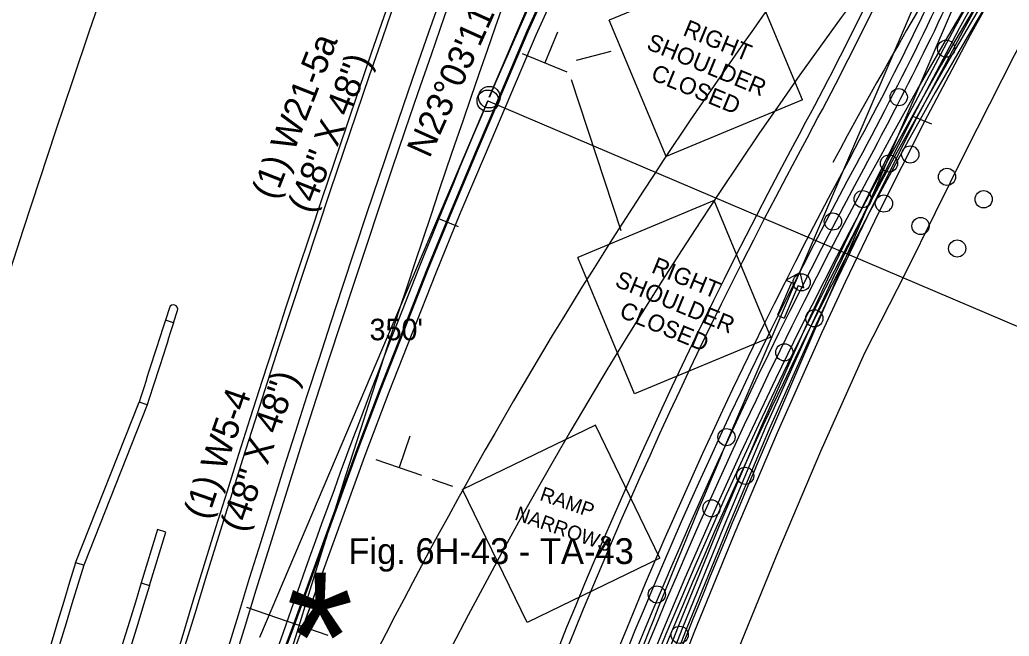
# Model space of a CAD drawing. Extents: x 659657 to 668193, y 633084 to 648639.
# Drawn here: x 661546.4 to 661776.7, y 641104.4 to 641247.7 of the extents above; entities that cross this region are included whole.
import ezdxf

# ---------------------------------------------------------------- set-up
doc = ezdxf.new("R2010")
doc.units = 0
for name, color, linetype in [('R_Border Prem', 7, 'Continuous'), ('R_Draft', 7, 'Continuous'), ('R_MOT_Stage 1A', 7, 'Continuous'), ('R_MOT_Stage 1A_Striping', 7, 'Continuous'), ('R_MOT_Stage 1B', 7, 'Continuous'), ('R_MOT_Stage 1B_Striping', 7, 'Continuous'), ('R_MOT_Stage 1C', 7, 'Continuous'), ('R_MOT_Stage 1C_Striping', 7, 'Continuous'), ('R_MOT_Stage 2', 7, 'Continuous'), ('R_MOT_Stage 2_Striping_PPM', 7, 'Continuous'), ('R_MOT_Stage 3_Striping_PPM', 7, 'Continuous'), ('R_MOT_Stage 4_Striping_PPM', 7, 'Continuous'), ('R_MOT_Stage 5_Striping_PPM', 7, 'Continuous'), ('S_EXISTING_ALIGNMENT', 7, 'Continuous'), ('T_SIGNAL CONTROL CABINET', 7, 'Continuous'), ('TEMP_DETECTION ZONE_Stage 2', 7, 'Continuous'), ('TEMP_SIGNAL_POLES_STAGE 3', 7, 'Continuous'), ('TEXT_TEMP_SIGNAL_POLES_STAGE 2', 7, 'Continuous')]:
    doc.layers.add(name, color=color, linetype=linetype)

msp = doc.modelspace()

# ---------------------------------------------------------------- linework, layer by layer
at = {"layer": 'R_Border Prem'}
msp.add_arc((665219.85, 639999.01), 3863.72, 156.12343, 201.98495, dxfattribs=at)
at = {"layer": 'R_MOT_Stage 1A'}
for points in [[(661690.86, 641084.08), (661699.68, 641106.74), (661709.23, 641130.12), (661719.07, 641153.39), (661729.49, 641176.72), (661734.96, 641188.51), (661742.81, 641204.85), (661753.48, 641226.01), (661764.17, 641246.15), (661771.4, 641259.24), (661776.94, 641268.8), (661789.32, 641290.7), (661801.96, 641312.47), (661814.78, 641334.13), (661827.85, 641355.66), (661841.14, 641377), (661849.52, 641390.35)], [(661692.73, 641083.37), (661701.54, 641106), (661711.08, 641129.35), (661720.91, 641152.59), (661731.31, 641175.89), (661736.77, 641187.66), (661744.61, 641203.96), (661755.26, 641225.09), (661765.93, 641245.2), (661773.14, 641258.26), (661778.67, 641267.8), (661791.06, 641289.7), (661803.68, 641311.46), (661816.49, 641333.1), (661829.55, 641354.62), (661842.83, 641375.94), (661851.27, 641389.37)]]:
    msp.add_lwpolyline(points, dxfattribs=at)
for centre in [(661748.71, 641214.33), (661731.33, 641178.31), (661715.22, 641141.7), (661699.97, 641104.72)]:
    msp.add_circle(centre, 2, dxfattribs=at)
at = {"layer": 'R_MOT_Stage 1A_Striping'}
for p, q in [((661655.68, 641229.74), (661701.73, 641337.94)), ((661655.68, 641229.74), (661701.73, 641337.94)), ((661602.25, 641104.17), (661655.32, 641228.89)), ((661602.25, 641104.17), (661655.32, 641228.89))]:
    msp.add_line(p, q, dxfattribs=at)
for points in [[(661694.6, 641082.67), (661703.39, 641105.26), (661712.93, 641128.58), (661722.74, 641151.79), (661733.13, 641175.06), (661738.57, 641186.8), (661746.4, 641203.08), (661757.03, 641224.17), (661767.69, 641244.25), (661774.88, 641257.27), (661780.41, 641266.81), (661792.8, 641288.71), (661805.41, 641310.45), (661818.21, 641332.07), (661831.26, 641353.57), (661844.53, 641374.88), (661853.01, 641388.39)], [(661713.61, 641101.19), (661723.08, 641124.36), (661732.83, 641147.42), (661743.05, 641170.31), (661752.62, 641188.93), (661766.4, 641216.91), (661777.94, 641239.5), (661790.01, 641261.46), (661802.34, 641283.25), (661814.9, 641304.89), (661827.64, 641326.42), (661840.62, 641347.81), (661853.85, 641369.05), (661862.25, 641382.42)], [(661655.32, 641228.89), (661867.57, 641138.56)], [(661758.71, 641223.46), (661754.08, 641225.35)], [(661599.17, 641111.17), (661618.06, 641104.61)]]:
    msp.add_lwpolyline(points, dxfattribs=at)
for centre in [(661655.68, 641229.74), (661655.32, 641228.89)]:
    msp.add_circle(centre, 2.5, dxfattribs=at)
for centre, radius, start, end in [((662973.69, 640668.84), 1432.39, 147.56037, 156.947), ((663412.67, 640481.02), 1909.86, 156.947, 165.06575)]:
    msp.add_arc(centre, radius, start, end, dxfattribs=at)
at = {"layer": 'R_MOT_Stage 1B'}
for centre in [(661750.97, 641229.73), (661753.65, 641216.42), (661762.19, 641211.21), (661747.52, 641205), (661770.73, 641206), (661735.65, 641200.81), (661756.05, 641199.77), (661764.58, 641194.55), (661728.36, 641186.68), (661710.89, 641150.68), (661694.67, 641114.1)]:
    msp.add_circle(centre, 2, dxfattribs=at)
for centre, radius, start, end in [((661058.38, 641584.99), 761.94, 331.55776, 336.77389), ((661058.38, 641584.99), 776.94, 331.55776, 336.77389), ((661058.38, 641584.99), 778.94, 331.55776, 336.15299), ((662755.3, 640665.85), 1167.92, 151.55776, 169.05116), ((662755.3, 640665.85), 1152.92, 151.55776, 169.05116), ((662755.3, 640665.85), 1150.92, 151.55776, 169.05116)]:
    msp.add_arc(centre, radius, start, end, dxfattribs=at)
at = {"layer": 'R_MOT_Stage 1B_Striping'}
for p, q in [((661655.68, 641229.74), (661701.73, 641337.94)), ((661655.68, 641229.74), (661701.73, 641337.94)), ((661602.25, 641104.17), (661655.32, 641228.89)), ((661602.25, 641104.17), (661655.32, 641228.89))]:
    msp.add_line(p, q, dxfattribs=at)
for points in [[(661655.32, 641228.89), (661867.57, 641138.56)], [(661648.53, 641199.56), (661643.9, 641201.45)], [(661599.17, 641111.17), (661618.06, 641104.61)]]:
    msp.add_lwpolyline(points, dxfattribs=at)
for centre in [(661655.68, 641229.74), (661655.32, 641228.89)]:
    msp.add_circle(centre, 2.5, dxfattribs=at)
for centre, radius, start, end in [((662973.69, 640668.84), 1432.39, 147.56037, 156.947), ((661058.38, 641584.99), 763.94, 331.55776, 336.77389), ((661058.38, 641584.99), 774.94, 331.55776, 336.77389), ((663412.67, 640481.02), 1909.86, 156.947, 165.06575), ((662755.3, 640665.85), 1165.92, 151.55776, 169.05116), ((662755.3, 640665.85), 1154.92, 151.55776, 169.05116)]:
    msp.add_arc(centre, radius, start, end, dxfattribs=at)
at = {"layer": 'R_MOT_Stage 1C'}
for points in [[(661599.69, 641078.64), (661609.82, 641105.49), (661614.93, 641119.59), (661620.04, 641133.7), (661625.17, 641147.83), (661630.51, 641161.92), (661635.87, 641175.5), (661641.39, 641189.49), (661647.07, 641203.44), (661652.96, 641217.3), (661658.83, 641231.15), (661664.71, 641245.03), (661670.95, 641258.81), (661677.34, 641272.5), (661681.59, 641281.56)], [(661601.61, 641078.07), (661611.69, 641104.8), (661616.81, 641118.91), (661621.92, 641133.02), (661627.04, 641147.14), (661632.37, 641161.19), (661637.73, 641174.77), (661643.24, 641188.74), (661648.92, 641202.67), (661654.8, 641216.52), (661660.67, 641230.37), (661666.55, 641244.23), (661672.77, 641257.97), (661679.15, 641271.66), (661683.4, 641280.71)], [(661614.93, 641119.59), (661620.04, 641133.7), (661625.17, 641147.83), (661630.51, 641161.92), (661635.87, 641175.5), (661641.39, 641189.49), (661647.07, 641203.44), (661652.96, 641217.3), (661658.83, 641231.15), (661664.71, 641245.03), (661670.95, 641258.81), (661677.34, 641272.5), (661681.59, 641281.56)], [(661616.81, 641118.91), (661621.92, 641133.02), (661627.04, 641147.14), (661632.37, 641161.19), (661637.73, 641174.77), (661643.24, 641188.74), (661648.92, 641202.67), (661654.8, 641216.52), (661660.67, 641230.37), (661666.55, 641244.23), (661672.77, 641257.97), (661679.15, 641271.66), (661683.4, 641280.71)], [(661610.34, 641106.95), (661614.93, 641119.59)], [(661612.24, 641106.31), (661616.81, 641118.91)]]:
    msp.add_lwpolyline(points, dxfattribs=at)
for centre in [(661762.02, 641241.02), (661742.57, 641206.03), (661724.35, 641170.39), (661707.38, 641134.14)]:
    msp.add_circle(centre, 2, dxfattribs=at)
for radius, start in [(1148.92, 140.57569), (1146.92, 140.57419)]:
    msp.add_arc((662755.3, 640665.85), radius, start, 160.92891, dxfattribs=at)
at = {"layer": 'R_MOT_Stage 1C_Striping'}
msp.add_lwpolyline([(661599.47, 641078.77), (661609.58, 641105.58), (661614.69, 641119.67), (661619.81, 641133.79), (661624.93, 641147.92), (661630.28, 641162), (661635.64, 641175.59), (661641.15, 641189.58), (661646.84, 641203.53), (661652.73, 641217.4), (661658.6, 641231.25), (661664.48, 641245.13), (661670.72, 641258.91), (661677.11, 641272.61), (661681.24, 641281.4)], dxfattribs=at)
for centre, radius, start, end in [((665219.85, 639999.01), 3799.97, 157.70222, 174.95222), ((665219.85, 639999.01), 3788.97, 157.70222, 174.95222), ((662755.3, 640665.85), 1144.92, 140.57268, 160.92891)]:
    msp.add_arc(centre, radius, start, end, dxfattribs=at)
at = {"layer": 'R_MOT_Stage 2'}
for p, q in [((661581.22, 641180.76), (661580.3, 641177.91)), ((661582.2, 641177.29), (661583.13, 641180.14)), ((661582.2, 641177.29), (661580.3, 641177.91)), ((661559.36, 641121.47), (661574.18, 641158.83)), ((661576.08, 641158.23), (661574.18, 641158.83)), ((661561.27, 641120.89), (661559.36, 641121.47))]:
    msp.add_line(p, q, dxfattribs=at)
msp.add_lwpolyline([(661576.08, 641158.23), (661561.27, 641120.89), (661561.27, 641120.89)], dxfattribs=at)
msp.add_lwpolyline([(661578.47, 641129.21), (661574.66, 641116.78), (661576.57, 641116.2), (661580.37, 641128.59)], close=True, dxfattribs=at)
for centre, radius, start, end in [((661582.17, 641180.45), 1, 342.0522, 162.0522), ((665219.85, 639999.01), 3825.72, 162.05222, 162.35222), ((665219.85, 639999.01), 3823.72, 162.05222, 162.35222), ((665219.85, 639999.01), 3828.72, 162.95222, 167.45222), ((665219.85, 639999.01), 3826.72, 162.95222, 167.45222), ((665219.85, 639999.01), 3812.72, 162.95222, 167.45222), ((665219.85, 639999.01), 3810.72, 162.95222, 167.45222)]:
    msp.add_arc(centre, radius, start, end, dxfattribs=at)
at = {"layer": 'R_MOT_Stage 2_Striping_PPM'}
for centre, radius, start, end in [((665219.85, 639999.01), 3798.72, 158.32294, 176.45222), ((662755.3, 640665.85), 1157.92, 140.57268, 151.71411), ((665219.85, 639999.01), 3786.72, 158.32294, 176.45222), ((662755.3, 640665.85), 1145.92, 140.57268, 169.05116), ((665219.85, 639999.01), 3774.72, 159.56642, 165.19143), ((662657.24, 640577.28), 1153.42, 140.57268, 146.42114), ((662657.24, 640577.28), 1138.42, 140.57268, 167.00403), ((662657.24, 640577.28), 1153.42, 146.42114, 160.42132)]:
    msp.add_arc(centre, radius, start, end, dxfattribs=at)
at = {"layer": 'R_MOT_Stage 3_Striping_PPM'}
for centre, radius, start, end in [((665219.85, 639999.01), 3798.72, 158.32294, 176.45222), ((662755.3, 640665.85), 1157.92, 140.57268, 151.71411), ((665219.85, 639999.01), 3786.72, 158.32294, 176.45222), ((662755.3, 640665.85), 1145.92, 140.57268, 169.05116), ((665219.85, 639999.01), 3774.72, 159.56642, 165.19143), ((662657.24, 640577.28), 1153.42, 140.57268, 146.42114), ((662657.24, 640577.28), 1138.42, 140.57268, 167.00403), ((662657.24, 640577.28), 1153.42, 146.42114, 160.42132)]:
    msp.add_arc(centre, radius, start, end, dxfattribs=at)
at = {"layer": 'R_MOT_Stage 4_Striping_PPM'}
for centre, radius, start, end in [((660777.38, 642087.58), 954.93, 348.72774, 348.72774), ((665219.85, 639999.01), 3798.72, 158.32294, 176.45222), ((662755.3, 640665.85), 1157.92, 140.57268, 151.71411), ((665219.85, 639999.01), 3786.72, 158.32294, 176.45222), ((662755.3, 640665.85), 1145.92, 140.57268, 169.05116), ((665219.85, 639999.01), 3774.72, 159.56642, 165.19143), ((662657.24, 640577.28), 1153.42, 140.57268, 146.42114), ((662657.24, 640577.28), 1138.42, 140.57268, 167.00403), ((662657.24, 640577.28), 1153.42, 146.42114, 160.42132)]:
    msp.add_arc(centre, radius, start, end, dxfattribs=at)
at = {"layer": 'R_MOT_Stage 5_Striping_PPM'}
for centre, radius, start, end in [((660777.38, 642087.58), 954.93, 348.72774, 348.72774), ((665219.85, 639999.01), 3798.72, 158.32294, 176.45222), ((662755.3, 640665.85), 1157.92, 140.57268, 151.71411), ((665219.85, 639999.01), 3786.72, 158.32294, 176.45222), ((662755.3, 640665.85), 1145.92, 140.57268, 169.05116), ((665219.85, 639999.01), 3774.72, 159.56642, 165.19143), ((662657.24, 640577.28), 1153.42, 140.57268, 146.42114), ((662657.24, 640577.28), 1138.42, 140.57268, 167.00403), ((662657.24, 640577.28), 1153.42, 146.42114, 160.42132)]:
    msp.add_arc(centre, radius, start, end, dxfattribs=at)
at = {"layer": 'S_EXISTING_ALIGNMENT'}
msp.add_line((661709.81, 641146.8), (661886.44, 641558.38), dxfattribs=at)
for centre, radius, start, end in [((662973.69, 640668.84), 1432.39, 147.56037, 156.947), ((663412.67, 640481.02), 1909.86, 156.947, 165.06575), ((663149.19, 640529.1), 1566.32, 156.77389, 164.91888)]:
    msp.add_arc(centre, radius, start, end, dxfattribs=at)
at = {"layer": 'T_SIGNAL CONTROL CABINET'}
for p, q in [((661717.62, 641143.45), (661775.48, 641278.25)), ((661724.7, 641187.19), (661727.92, 641188.99)), ((661727.92, 641188.99), (661728.83, 641185.41)), ((661725.99, 641186.63), (661722.73, 641179.03)), ((661724.7, 641187.19), (661725.99, 641186.63)), ((661727.54, 641185.97), (661724.28, 641178.36)), ((661727.54, 641185.97), (661728.83, 641185.41)), ((661722.73, 641179.03), (661724.28, 641178.36))]:
    msp.add_line(p, q, dxfattribs=at)
msp.add_lwpolyline([(661850.39, 641389.86), (661841.98, 641376.47), (661828.7, 641355.14), (661815.64, 641333.61), (661802.82, 641311.96), (661790.19, 641290.2), (661777.8, 641268.3), (661772.27, 641258.75), (661765.05, 641245.67), (661754.37, 641225.55), (661743.71, 641204.4), (661735.86, 641188.09), (661730.4, 641176.3), (661719.99, 641152.99), (661710.16, 641129.73), (661700.61, 641106.37), (661691.79, 641083.73)], dxfattribs=at)
msp.add_arc((663149.19, 640529.1), 1557.82, 156.77389, 164.90188, dxfattribs=at)
at = {"layer": 'TEMP_DETECTION ZONE_Stage 2'}
for p, q in [((661668.68, 641237.81), (661671.61, 641244.9)), ((661673.79, 641235.52), (661663.39, 641239.81)), ((661674.76, 641233.86), (661686.28, 641198.71)), ((661708.02, 641205.68), (661676.27, 641192.47)), ((661721.23, 641173.92), (661708.02, 641205.68)), ((661689.48, 641160.73), (661676.27, 641192.47)), ((661721.23, 641173.92), (661689.48, 641160.73)), ((661680.39, 641153.48), (661649.44, 641138.47)), ((661695.4, 641122.54), (661680.39, 641153.48)), ((661634.76, 641143.73), (661637.28, 641150.99)), ((661640, 641141.75), (661629.37, 641145.43)), ((661642.36, 641140.93), (661647.08, 641139.29)), ((661664.46, 641107.55), (661649.44, 641138.47)), ((661695.4, 641122.54), (661664.46, 641107.55))]:
    msp.add_line(p, q, dxfattribs=at)
at = {"layer": 'TEMP_SIGNAL_POLES_STAGE 3'}
for p, q in [((661655.68, 641229.74), (661701.73, 641337.94)), ((661655.68, 641229.74), (661701.73, 641337.94)), ((661602.25, 641104.17), (661655.32, 641228.89)), ((661602.25, 641104.17), (661655.32, 641228.89))]:
    msp.add_line(p, q, dxfattribs=at)
for points in [[(661655.32, 641228.89), (661867.57, 641138.56)], [(661648.53, 641199.56), (661643.9, 641201.45)], [(661599.17, 641111.17), (661618.06, 641104.61)]]:
    msp.add_lwpolyline(points, dxfattribs=at)
for centre in [(661655.68, 641229.74), (661655.32, 641228.89)]:
    msp.add_circle(centre, 2.5, dxfattribs=at)
msp.add_arc((662973.69, 640668.84), 1432.39, 147.56037, 156.947, dxfattribs=at)
at = {"layer": 'TEXT_TEMP_SIGNAL_POLES_STAGE 2'}
for p, q in [((661715.36, 641260.86), (661683.61, 641247.65)), ((661728.57, 641229.11), (661715.36, 641260.86)), ((661696.82, 641215.91), (661683.61, 641247.65)), ((661668.68, 641237.81), (661671.61, 641244.9)), ((661673.79, 641235.52), (661663.39, 641239.81)), ((661676, 641238.32), (661684.04, 641240.41)), ((661728.57, 641229.11), (661696.82, 641215.91)), ((661680.39, 641153.48), (661649.44, 641138.47)), ((661695.4, 641122.54), (661680.39, 641153.48)), ((661634.76, 641143.73), (661637.28, 641150.99)), ((661640, 641141.75), (661629.37, 641145.43)), ((661642.36, 641140.93), (661647.08, 641139.29)), ((661664.46, 641107.55), (661649.44, 641138.47)), ((661695.4, 641122.54), (661664.46, 641107.55))]:
    msp.add_line(p, q, dxfattribs=at)

# ---------------------------------------------------------------- texts
at = {"layer": 'R_Draft'}
msp.add_text('*', height=30, dxfattribs=at).set_placement((661608.45, 641089.18))
at = {"layer": 'R_MOT_Stage 1A_Striping'}
msp.add_text('N23%%d03\'11"E', height=6, rotation=65.7398, dxfattribs=at).set_placement((661641.74, 641215.34))
at = {"layer": 'R_MOT_Stage 1B_Striping'}
msp.add_text('N23%%d03\'11"E', height=6, rotation=65.7398, dxfattribs=at).set_placement((661641.74, 641215.34))
at = {"layer": 'T_SIGNAL CONTROL CABINET'}
for s, height, p in [("350'", 5, (661627.8, 641173.21)), ('Fig. 6H-43 - TA-43', 6, (661622.87, 641121.18))]:
    msp.add_text(s, height=height, dxfattribs=at).set_placement(p)
at = {"layer": 'TEMP_DETECTION ZONE_Stage 2'}
for s, height, rotation, p in [('(1) W21-5a', 6, 68.5677, (661605.79, 641205.62)), ('(48" X 48")', 6, 68.5677, (661614.19, 641202.42)), ('RIGHT', 3.94, 337.5875, (661693.17, 641189.05)), ('SHOULDER', 3.94, 337.5871, (661684.67, 641185.85)), ('CLOSED', 3.94, 337.5871, (661685.69, 641178.72)), ('(48" X 48")', 6, 70.8782, (661598.59, 641128.26)), ('(1) W5-4', 6, 70.8782, (661590.09, 641131.21)), ('RAMP', 3.339, 340.8787, (661667.21, 641136.1)), ('NARROWS', 3.339, 340.8782, (661661.39, 641131.56))]:
    msp.add_text(s, height=height, rotation=rotation, dxfattribs=at).set_placement(p)
at = {"layer": 'TEMP_SIGNAL_POLES_STAGE 3'}
msp.add_text('N23%%d03\'11"E', height=6, rotation=65.7398, dxfattribs=at).set_placement((661641.74, 641215.34))
at = {"layer": 'TEXT_TEMP_SIGNAL_POLES_STAGE 2'}
for s, height, rotation, p in [('RIGHT', 3.94, 337.5875, (661700.51, 641244.23)), ('SHOULDER', 3.94, 337.5871, (661692.01, 641241.03)), ('CLOSED', 3.94, 337.5871, (661693.03, 641233.91)), ('(48" X 48")', 6, 70.8782, (661598.59, 641128.26)), ('(1) W5-4', 6, 70.8782, (661590.09, 641131.21)), ('RAMP', 3.339, 340.8787, (661667.21, 641136.1)), ('NARROWS', 3.339, 340.8782, (661661.39, 641131.56))]:
    msp.add_text(s, height=height, rotation=rotation, dxfattribs=at).set_placement(p)

doc.saveas('drawing.dxf')
